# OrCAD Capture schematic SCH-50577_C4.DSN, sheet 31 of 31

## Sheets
31 15 PHY0_RMII/MII_ECAT0: size C
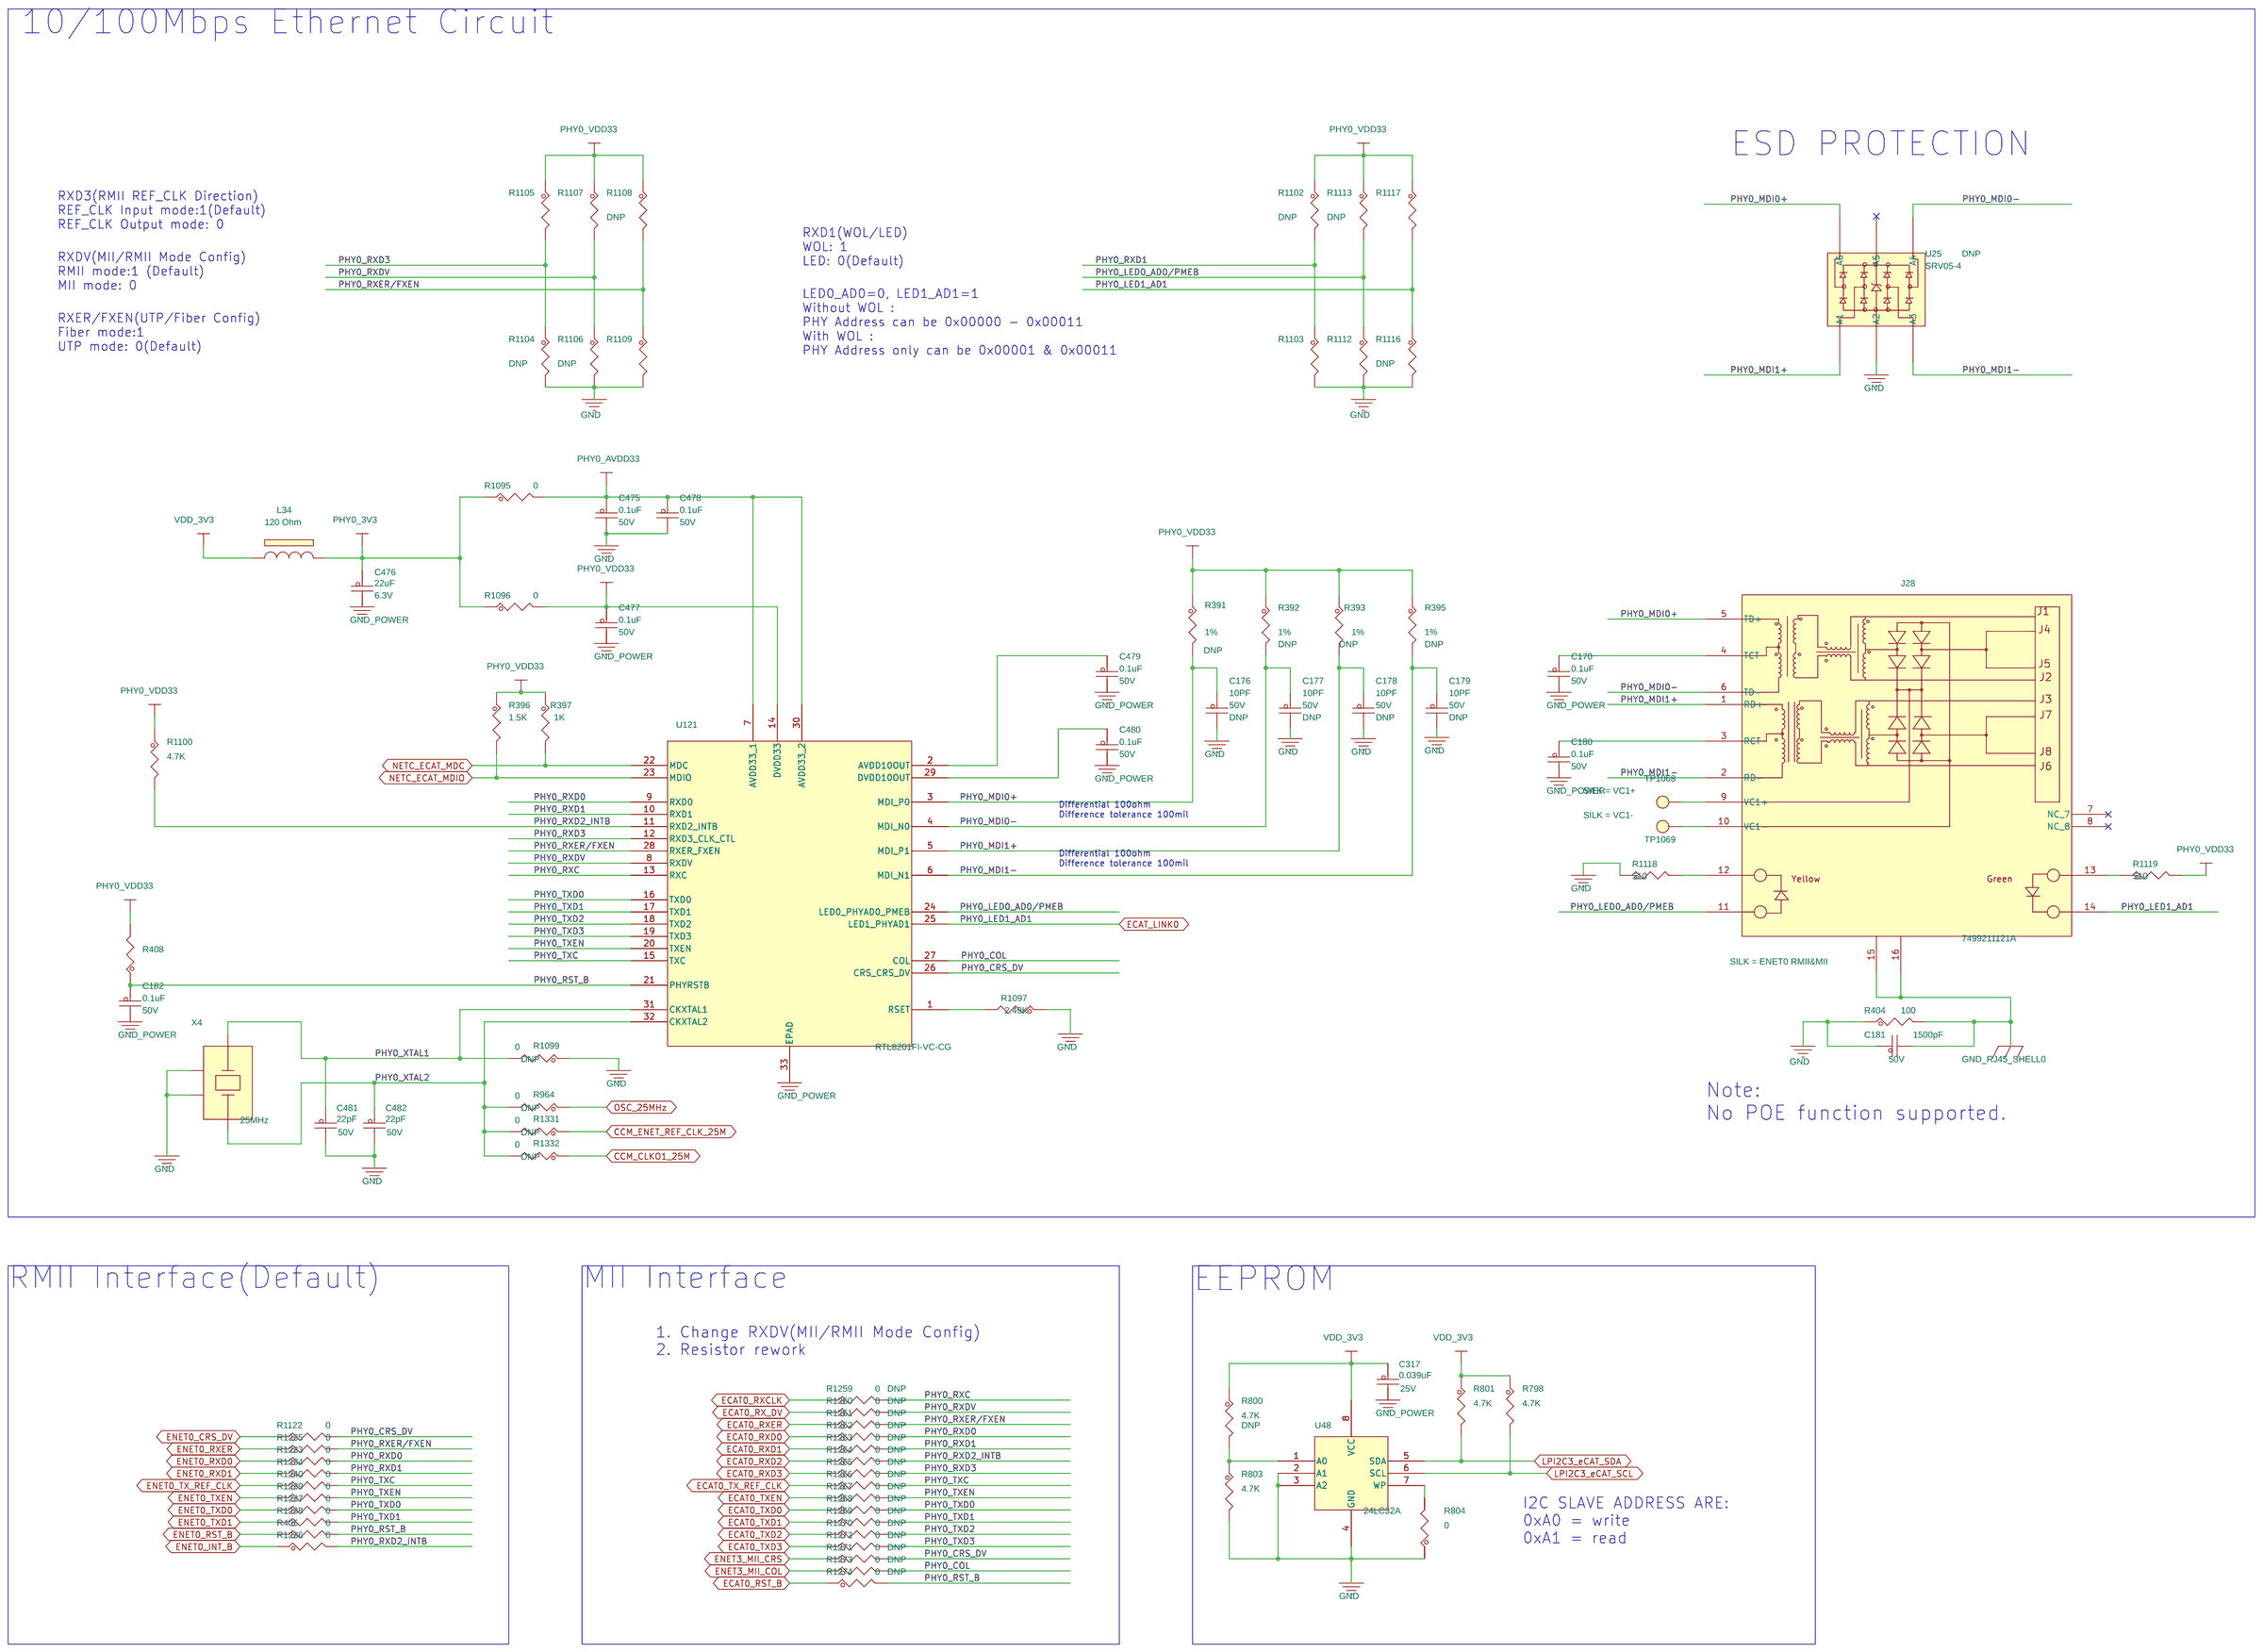
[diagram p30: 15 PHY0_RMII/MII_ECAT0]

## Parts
C170  0.1uF  [0402_CC]
C176  10PF  [0402_CC]
C177  10PF  [0402_CC]
C178  10PF  [0402_CC]
C179  10PF  [0402_CC]
C180  0.1uF  [0402_CC]
C181  1500pF  [0402_CC]
C182  0.1uF  [0402_CC]
C317  0.039uF  [0402_CC]
C475  0.1uF  [0402_CC]
C476  22uF  [CC0603_OV]
C477  0.1uF  [0402_CC]
C478  0.1uF  [0402_CC]
C479  0.1uF  [0402_CC]
C480  0.1uF  [0402_CC]
C481  22pF  [0402_CC]
C482  22pF  [0402_CC]
J28  7499211121A  [con_rj45_2led_th_a]
L34  120 Ohm  [0402_CC]
R391  49.9  [RC0603_OV]
R392  49.9  [RC0603_OV]
R393  49.9  [RC0603_OV]
R395  49.9  [RC0603_OV]
R396  1.5K  [0402_CC]
R397  1K  [0402_CC]
R404  100  [0402_CC]
R405  0  [0402_CC]
R408  10K  [0402_CC]
R798  4.7K  [0402_CC]
R800  4.7K  [0402_CC]
R801  4.7K  [0402_CC]
R803  4.7K  [0402_CC]
R804  0  [0402_CC]
R964  0  [0402_CC]
R1095  0  [0402_CC]
R1096  0  [0402_CC]
R1097  2.49K  [RC0402_25]
R1099  0  [0402_CC]
R1100  4.7K  [0402_CC]
R1102  4.7K  [0402_CC]
R1103  4.7K  [0402_CC]
R1104  4.7K  [0402_CC]
R1105  4.7K  [0402_CC]
R1106  4.7K  [0402_CC]
R1107  4.7K  [0402_CC]
R1108  4.7K  [0402_CC]
R1109  4.7K  [0402_CC]
R1112  4.7K  [0402_CC]
R1113  4.7K  [0402_CC]
R1116  4.7K  [0402_CC]
R1117  4.7K  [0402_CC]
R1118  510  [RC0402_25]
R1119  510  [RC0402_25]
R1122  0  [0402_CC]
R1233  0  [0402_CC]
R1234  0  [0402_CC]
R1235  0  [0402_CC]
R1236  0  [0402_CC]
R1237  0  [0402_CC]
R1238  0  [0402_CC]
R1239  0  [0402_CC]
R1240  0  [0402_CC]
R1259  0  [0402_CC]
R1260  0  [0402_CC]
R1261  0  [0402_CC]
R1262  0  [0402_CC]
R1263  0  [0402_CC]
R1264  0  [0402_CC]
R1265  0  [0402_CC]
R1266  0  [0402_CC]
R1267  0  [0402_CC]
R1268  0  [0402_CC]
R1269  0  [0402_CC]
R1270  0  [0402_CC]
R1271  0  [0402_CC]
R1272  0  [0402_CC]
R1273  0  [0402_CC]
R1274  0  [0402_CC]
R1331  0  [0402_CC]
R1332  0  [0402_CC]
TP1068  TP_35MIL  [testpoint_35mil]
TP1069  TP_35MIL  [testpoint_35mil]
U25  SRV05-4  [SOT23_S6]
U48  24LC32A  [TSSOP8]
U121  RTL8201FI-VC-CG  [qfn32_0p5_5x5_s142ep]
X4  25MHz  [xtal4_5p2x3p4mm_sm]

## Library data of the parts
C170 C180 C182 C475 C477-C480 = CAP_NP: CAP CER 0.1uF 50V 10% X7R AEC-Q200 0402; AGILE_PN: 150-79461; CAD_APPROVED: Yes; FPLIST: CC0402_25,CC0402_HD,0402_CC,CC0402_18,capc0402_l; HEIGHT: 0.55MM; MFG_NAME01: MURATA; MFG_PN01: GCM155R71H104KE02D; Package Size: 0402; ROHS: Yes; Tolerance: 10%; VOLTAGE: 50V
C176-C179 = CAP_NP: CAP CER 10PF 50V 5% C0G 0402; AGILE_PN: 150-75265; ASSY_OPT: DNP; CAD_APPROVED: YES; FPLIST: CC0402_25,CC0402_HD,0402_CC; HEIGHT: 0.635MM; MFG_NAME01: AVX; MFG_PN01: 04025A100JAT2A; Package Size: 0402; Package Type: 7; ROHS: Yes; TOL: 5%; Tolerance: 5%; VOLTAGE: 50V
C181 = CAP_NP: CAP CER 1500PF 50V 10% X7R 0402; AGILE_PN: 150-76273; CAD_APPROVED: Yes; FPLIST: CC0402_25,CC0402_HD,0402_CC; HEIGHT: 0.55MM; MFG_NAME01: AVX; MFG_PN01: 04025C152KAT2A; ROHS: Yes; Tolerance: 10%; VOLTAGE: 50V
C317 = CAP_NP: CAP CER 0.039UF 25V 10% X7R 0402; AGILE_PN: 150-80295; CAD_APPROVED: Yes; FPLIST: CC0402_25,CC0402_HD,0402_CC,capc0402_l; HEIGHT: 0.56MM; MFG_NAME01: KEMET; MFG_PN01: C0402C393K3RAC7867; ROHS: Yes; VOLTAGE: 25V
C476 = CAP_NP: CAP CER 22uF 6.3V 20% X6S 0603; AGILE_PN: 150-79717; CAD_APPROVED: Yes; FPLIST: CC0603_OV,CC0603,0603_CC_NSP; HEIGHT: 1MM; MFG_NAME01: MURATA; MFG_PN01: GRM188C80J226ME15D; Package Size: 0603; Package Type: 180mm ReelPAPER W8P4; ROHS: Yes; Tolerance: 20%; VOLTAGE: 6.3V
C481 C482 = CAP_NP: CAP CER 22pF 50V 2% C0G HIGH-Q 0402; AGILE_PN: 150-79896; CAD_APPROVED: Yes; FPLIST: CC0402_25,CC0402_HD,0402_CC,capc0402_l; HEIGHT: 0.55MM; MFG_NAME01: MURATA; MFG_PN01: GJM1555C1H220GB01D; Package Size: 0402; Package Type: 180mm Reel PAPER W8P2; ROHS: Yes; Temp Range: -55 to +125°C; Tolerance: 2%; VOLTAGE: 50V
J28 = RJ45_7499211121A: CON 14 RJ-45 RA SHLD TH G/Y LEDS 50MIL SP 549H AU 140L; AGILE_PN: 210-81885; CAD_APPROVED: Yes; HEIGHT: 13.95MM; MFG_NAME01: WURTH ELEKTRONIK EISOS GMBH & CO. KG (ELECTRONIC & ELECTROMEHANICAL COMP); ROHS: Yes; SILK: ENET0 RMII&MII; Temp Range: -40 to 85C; Temp_Range: -40 to 85C
L34 = INDUCTOR_FERRITE: IND FER BEAD 120 OHM@100MHZ 0.5A 25% 0402; AGILE_PN: 180-77771; CAD_APPROVED: Yes; FPLIST: IND_0402,0402_CC; HEIGHT: 0.55MM; MFG_NAME01: MURATA; MFG_PN01: BLM15AG121SN1D; PART_TYPE: FERRITE\BEAD; Package Size: 0402; ROHS: Yes; Tolerance: 25%
R391-R393 R395 = RES: RES MF 49.9 OHM 1/10W 1% 0603; AGILE_PN: 470-75432; ASSY_OPT: DNP; CAD_APPROVED: Yes; FPLIST: RC0603_OV,RC0603,0603_CC; HEIGHT: 0.55 MM; MFG_NAME01: BOURNS; MFG_PN01: CR0603-FX-49R9ELF; ROHS: Yes; TOL: 1%; Tolerance: 1%
R396 = RES: RES MF 1.5K 1/16W 5% 0402; AGILE_PN: 470-76303; CAD_APPROVED: Yes; FPLIST: RC0402_25,RC0402_HD,0402_CC; HEIGHT: 0.40 MM; MFG_NAME01: VISHAY INTERTECHNOLOGY; MFG_PN01: CRCW04021K50JNED; ROHS: Yes; Tolerance: 5%; VOLTAGE: 1/16W
R397 = RES: RES MF 1.0K 1/16W 5% 0402; AGILE_PN: 470-75555; CAD_APPROVED: Yes; FPLIST: RC0402_25,RC0402_HD,RC0402_X2,0402_CC; HEIGHT: 0.41mm; MFG_NAME01: VISHAY INTERTECHNOLOGY; MFG_PN01: CRCW04021K00JNED; ROHS: Yes; Tolerance: 5%
R404 = RES: RES MF 100 OHM 1/16W 5% 0402; AGILE_PN: 470-75591; CAD_APPROVED: Yes; FPLIST: RC0402_25,RC0402_HD,RC0402_X2,0402_CC; HEIGHT: 0.45mm; MFG_NAME01: NIC COMPONENTS CORP; MFG_PN01: NRCL04J101TRF; ROHS: Yes; Tolerance: 5%
R405 R1095 R1096 R1233-R1240 = RES: RES MF ZERO OHM 1/16W 5% 0402; AGILE_PN: 470-75394; CAD_APPROVED: Yes; FPLIST: RC0402_25,RC0402_HD,RC0402_X2,0402_CC; HEIGHT: 0.45 MM; MFG_NAME01: ROHM; MFG_PN01: MCR01MZPJ000; ROHS: Yes; Tolerance: 5%; VOLTAGE: 1/16W
R408 = RES: RES MF 10K 1/16W 5% 0402; AGILE_PN: 470-75557; CAD_APPROVED: Yes; FPLIST: RC0402_25,RC0402_HD,0402_CC; HEIGHT: 0.4 MM; MFG_NAME01: VISHAY INTERTECHNOLOGY; MFG_PN01: CRCW040210K0JNED; ROHS: Yes; TOL: 5%; Tolerance: 5%
R798 R801 R803 R1100 = RES: RES MF 4.7K 1/16W 5% 0402; AGILE_PN: 470-75626; CAD_APPROVED: Yes; FPLIST: RC0402_25,RC0402_HD,0402_CC; HEIGHT: 0.41mm; MFG_NAME01: NIC COMPONENTS CORP; MFG_PN01: NRCL04J472TRF; ROHS: Yes; Tolerance: 5%
R800 = RES: RES MF 4.7K 1/16W 5% 0402; AGILE_PN: 470-75626; ASSY_OPT: DNP; CAD_APPROVED: Yes; FPLIST: RC0402_25,RC0402_HD,0402_CC; HEIGHT: 0.41mm; MFG_NAME01: NIC COMPONENTS CORP; MFG_PN01: NRCL04J472TRF; ROHS: Yes; Tolerance: 5%
R804 R1122 = RES: RES MF ZERO OHM 1/16W 5% 0402; AGILE_PN: 470-75394; CAD_APPROVED: Yes; FPLIST: RC0402_25,RC0402_HD,RC0402_X2,0402_CC; HEIGHT: 0.45 MM; MFG_NAME01: YAGEO AMERICA; MFG_PN01: RC0402JR-070RL; ROHS: Yes; Tolerance: 5%; VOLTAGE: 1/16W
R964 R1099 R1259-R1274 R1331 R1332 = RES: RES MF ZERO OHM 1/16W 5% 0402; AGILE_PN: 470-75394; ASSY_OPT: DNP; CAD_APPROVED: Yes; FPLIST: RC0402_25,RC0402_HD,RC0402_X2,0402_CC; HEIGHT: 0.45 MM; MFG_NAME01: ROHM; MFG_PN01: MCR01MZPJ000; ROHS: Yes; Tolerance: 5%; VOLTAGE: 1/16W
R1097 = RES: RES MF 2.49K 1/16W 1% 0402; AGILE_PN: 470-76080; CAD_APPROVED: Yes; FPLIST: RC0402_25,RC0402_HD,0402_CC; HEIGHT: 0.4 MM; MFG_NAME01: BOURNS; MFG_PN01: CR0402-FX-2491GLF; ROHS: Yes; Tolerance: 1%
R1102 R1104 R1106 R1108 R1113 R1116 = RES: RES MF 4.70K 1/16W 1% 0402; AGILE_PN: 470-75418; ASSY_OPT: DNP; CAD_APPROVED: Yes; FPLIST: RC0402_25,RC0402_HD,0402_CC; HEIGHT: 0.4mm; MFG_NAME01: WALSIN TECHNOLOGY CORP.; MFG_PN01: WR04X4701FTL; ROHS: Yes; Tolerance: 1%; VOLTAGE: 1/16W
R1103 R1105 R1107 R1109 R1112 R1117 = RES: RES MF 4.70K 1/16W 1% 0402; AGILE_PN: 470-75418; CAD_APPROVED: Yes; FPLIST: RC0402_25,RC0402_HD,0402_CC; HEIGHT: 0.4mm; MFG_NAME01: WALSIN TECHNOLOGY CORP.; MFG_PN01: WR04X4701FTL; ROHS: Yes; Tolerance: 1%; VOLTAGE: 1/16W
R1118 R1119 = RES: RES MF 510 OHM 1/16W 1% AEC-Q200 0402; AGILE_PN: 470-80725; CAD_APPROVED: Yes; FPLIST: RC0402_25,RC0402_HD,0402_CC; HEIGHT: 0.4 MM; MFG_NAME01: VISHAY INTERTECHNOLOGY; MFG_PN01: CRCW0402510RFKED; ROHS: Yes; Tolerance: 1%
TP1068 = T_POINT_R: TEST POINT PAD .035 SMT, no part to order; AGILE_PN: 510-75618; CAD_APPROVED: Yes; HEIGHT: 0.1MM; ROHS: Yes; SILK: VC1+
TP1069 = T_POINT_R: TEST POINT PAD .035 SMT, no part to order; AGILE_PN: 510-75618; CAD_APPROVED: Yes; HEIGHT: 0.1MM; ROHS: Yes; SILK: VC1-
U25 = SRV05-4: DIODE TVS ARRAY 12A 5V 300W SOT23_S6; AGILE_PN: 480-75205; ASSY_OPT: DNP; CAD_APPROVED: Yes; HEIGHT: 1.45mm; MFG_NAME01: SEMTECH CORP; MFG_PN01: SRV05-4.TCT; ROHS: Yes; Rated Voltage: 5V; VOLTAGE: 5V
U48 = Atmel_Serial_EEPROM_64K-1: IC MEM EEPROM 32KBIT I2C 2.5-5.5V TSSOP8; AGILE_PN: 334-77764; CAD_APPROVED: Yes; HEIGHT: 1.2MM; MFG_NAME01: MICROCHIP TECHNOLOGY INC; MFG_PN01: 24LC32A-E/ST; ROHS: Yes; VOLTAGE: 2.5-5.5V
U121 = RTL8201FI: IC SINGLE CHIP/PORT 10/100M ETHERNET 2.97-3.63V QFN32; AGILE_PN: 312-83298; CAD_APPROVED: Yes; HEIGHT: 1MM; MFG_NAME01: REALTEK SEMICONDUCTOR; ROHS: Yes; Temp Range: -40C to +85C; VOLTAGE: 2.97-3.63V
X4 = XTAL_13: XTAL 25MHz 13PF 5x3.2mm SMT; AGILE_PN: 230-78201; CAD_APPROVED: Yes; EN: 108-1-00013; HEIGHT: 1MM; MFG_NAME01: CTS; MFG_PN01: 405C35B25M00000; ROHS: Yes; Temp Range: -20C to +70C; Temp_Range: -20C to +70C

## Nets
GND: C170.2 C176.2 C177.2 C178.2 C179.2 C180.2 C181.1 C182.2 C317.2 C475.2 C476.2 C477.2 C478.2 C479.2 C480.2 C481.2 C482.2 R404.1 R803.2 R804.1 R1097.1 R1099.1 R1103.2 R1104.2 R1106.2 R1109.2 R1112.2 R1116.2 R1118.1 U25.2(A2) U48.2(A1) U48.3(A2) U48.4(GND) U121.33(EPAD) X4.2 X4.4 ; also on sheet 2 5 6 7 8 9 10 11 12 13 14 15 16 17 18 19 20 21 22 23 24 25 26 27 28 29 30
GND_RJ45_SHELL0: C181.2 J28.15 J28.16 R404.2
CCM_CLKO1_25M: R1332.1 ; also on sheet 9 30
CCM_ENET_REF_CLK_25M: R1331.1 ; also on sheet 8 30
ECAT0_RST_B: R1274.1 ; also on sheet 8
ECAT0_RX_DV: R1260.1 ; also on sheet 18
ECAT0_RXCLK: R1259.1 ; also on sheet 18
ECAT0_RXD0: R1262.1 ; also on sheet 18
ECAT0_RXD1: R1263.1 ; also on sheet 18
ECAT0_RXD2: R1264.1 ; also on sheet 18
ECAT0_RXD3: R1265.1 ; also on sheet 18
ECAT0_RXER: R1261.1 ; also on sheet 9
ECAT0_TX_REF_CLK: R1266.1 ; also on sheet 18
ECAT0_TXD0: R1268.1 ; also on sheet 18
ECAT0_TXD1: R1269.1 ; also on sheet 18
ECAT0_TXD2: R1270.1 ; also on sheet 18
ECAT0_TXD3: R1272.1 ; also on sheet 18
ECAT0_TXEN: R1267.1 ; also on sheet 18
ECAT_LINK0: J28.14 R1116.1 R1117.2 U121.25(LED1_PHYAD1) ; also on sheet 8
ENET0_CRS_DV: R1122.1 ; also on sheet 9
ENET0_INT_B: R1236.1 ; also on sheet 8
ENET0_RST_B: R405.1 ; also on sheet 8
ENET0_RXD0: R1233.1 ; also on sheet 9
ENET0_RXD1: R1234.1 ; also on sheet 9
ENET0_RXER: R1235.1 ; also on sheet 9
ENET0_TX_REF_CLK: R1240.1 ; also on sheet 9
ENET0_TXD0: R1237.1 ; also on sheet 9
ENET0_TXD1: R1238.1 ; also on sheet 9
ENET0_TXEN: R1239.1 ; also on sheet 9
ENET3_MII_COL: R1273.1 ; also on sheet 9
ENET3_MII_CRS: R1271.1 ; also on sheet 9
I3C2_SCL: R798.2 U48.6(SCL) ; also on sheet 8 24 25 26
I3C2_SDA: R801.2 U48.5(SDA) ; also on sheet 8 24 25 26
NETC_ECAT_MDC: R397.2 U121.22(MDC) ; also on sheet 8 16 17 18 29 30
NETC_ECAT_MDIO: R396.2 U121.23(MDIO) ; also on sheet 8 16 17 18 29 30
OSC_25MHz: R964.1 ; also on sheet 30
PHY0_3V3: C476.1 L34.2 R1095.1 R1096.1
PHY0_AVDD33: C475.1 C478.1 R1095.2 U121.7(AVDD33_1) U121.30(AVDD33_2)
PHY0_COL: R1273.2 U121.27(COL)
PHY0_CRS_DV: R1122.2 R1271.2 U121.26(CRS_CRS_DV)
PHY0_LED0_AD0/PMEB: J28.11 R1112.1 R1113.2 U121.24(LED0_PHYAD0_PMEB)
PHY0_MDI0+: C176.1 J28.5(TD+) R391.2 U25.6(A6) U121.3(MDI_P0)
PHY0_MDI0-: C177.1 J28.6(TD-) R392.2 U25.4(A4) U121.4(MDI_N0)
PHY0_MDI1+: C178.1 J28.1(RD+) R393.2 U25.1(A1) U121.5(MDI_P1)
PHY0_MDI1-: C179.1 J28.2(RD-) R395.2 U25.3(A3) U121.6(MDI_N1)
PHY0_RST_B: C182.1 R405.2 R408.1 R1274.2 U121.21(PHYRSTB)
PHY0_RXC: R1259.2 U121.13(RXC)
PHY0_RXD0: R1233.2 R1262.2 U121.9(RXD0)
PHY0_RXD1: R1102.2 R1103.1 R1234.2 R1263.2 U121.10(RXD1)
PHY0_RXD2_INTB: R1100.2 R1236.2 R1264.2 U121.11(RXD2_INTB)
PHY0_RXD3: R1104.1 R1105.2 R1265.2 U121.12(RXD3_CLK_CTL)
PHY0_RXDV: R1106.1 R1107.2 R1260.2 U121.8(RXDV)
PHY0_RXER/FXEN: R1108.2 R1109.1 R1235.2 R1261.2 U121.28(RXER_FXEN)
PHY0_TXC: R1240.2 R1266.2 U121.15(TXC)
PHY0_TXD0: R1237.2 R1268.2 U121.16(TXD0)
PHY0_TXD1: R1238.2 R1269.2 U121.17(TXD1)
PHY0_TXD2: R1270.2 U121.18(TXD2)
PHY0_TXD3: R1272.2 U121.19(TXD3)
PHY0_TXEN: R1239.2 R1267.2 U121.20(TXEN)
PHY0_VDD33: C477.1 R391.1 R392.1 R393.1 R395.1 R396.1 R397.1 R408.2 R1096.2 R1100.1 R1102.1 R1105.1 R1107.1 R1108.1 R1113.1 R1117.1 R1119.2 U121.14(DVDD33)
PHY0_XTAL1: C481.1 R1099.2 U121.31(CKXTAL1) X4.1
PHY0_XTAL2: C482.1 R964.2 R1331.2 R1332.2 U121.32(CKXTAL2) X4.3
SENSOR_3V3: C317.1 L34.1 R798.1 R800.1 R801.1 U48.8(VCC) ; also on sheet 2 5 6 7 8 9 10 11 12 13 14 15 16 17 18 19 20 21 22 23 24 25 26 27 28 29 30
N104649727: R804.2 U48.7(WP)
N104649749: R800.2 R803.1 U48.1(A0)
N105541476: C479.1 U121.2(AVDD10OUT)
N105544244: R1097.2 U121.1(RSET)
N105551352: C480.1 U121.29(DVDD10OUT)
N105554209: C170.1 J28.4(TCT)
N105554214: C180.1 J28.3(RCT)
N105554264: J28.9(VC1+) TP1068.1(TP)
N106559790: J28.13 R1119.1
N106561451: J28.12 R1118.2
N107431729: J28.10(VC1-) TP1069.1(TP)

Not connected (* = marked no-connect by the designer): J28 7(NC)* 8(NC)*; U25 5(A5)*

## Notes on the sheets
sheet 31
- 10/100Mbps Ethernet Circuit
- ESD PROTECTION
- RXD3(RMII REF_CLK Direction)
  REF_CLK Input mode:1(Default)
  REF_CLK Output mode: 0
- RXD1(WOL/LED)
  WOL: 1
  LED: 0(Default)
- RXDV(MII/RMII Mode Config)
  RMII mode:1 (Default)
  MII mode: 0
- LED0_AD0=0, LED1_AD1=1
  Without WOL :
  PHY Address can be 0x00000 - 0x00011
  With WOL :
  PHY Address only can be 0x00001 & 0x00011
- RXER/FXEN(UTP/Fiber Config)
  Fiber mode:1
  UTP mode: 0(Default)
- Differential 100ohm
  Difference tolerance 100mil
- Differential 100ohm
  Difference tolerance 100mil
- Note:
  No POE function supported.
- RMII Interface(Default)
- MII Interface
- EEPROM
- 1. Change RXDV(MII/RMII Mode Config)
  2. Resistor rework
- I2C SLAVE ADDRESS ARE:
  0xA0 = write
  0xA1 = read
